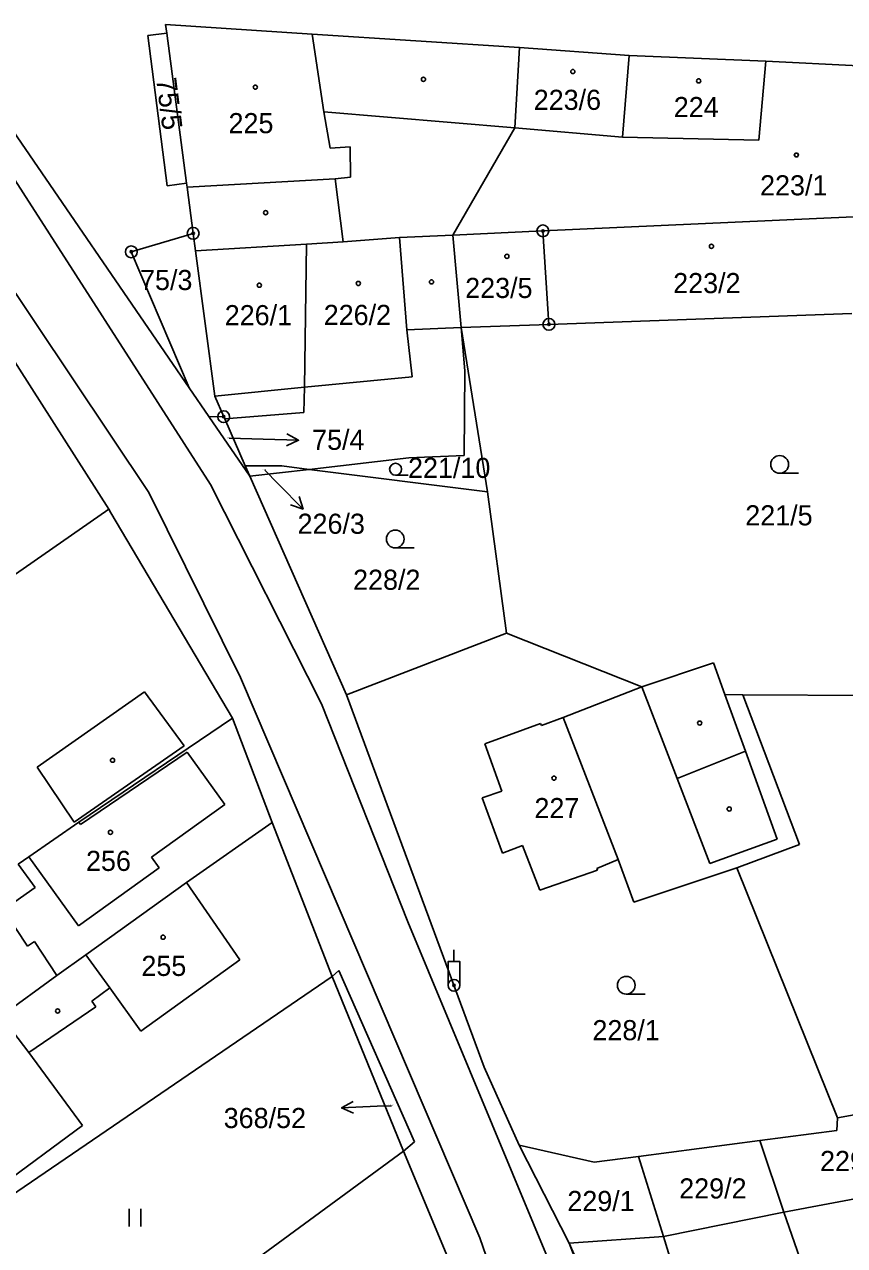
# Model space of a CAD drawing. Extents: x -762263 to -760336, y -1154405 to -1152076.
# Drawn here: x -761538.5 to -761469.2, y -1152630.1 to -1152526.9 of the extents above; entities that cross this region are included whole.
import ezdxf

# ---------------------------------------------------------------- set-up
doc = ezdxf.new("R2010")
doc.units = 0
for name, color, linetype in [('Vrstva 1', 7, 'Continuous'), ('Vrstva 16', 7, 'Continuous'), ('Vrstva 18', 7, 'Continuous'), ('Vrstva 19', 7, 'Continuous'), ('Vrstva 24', 7, 'Continuous'), ('Vrstva 25', 7, 'Continuous'), ('Vrstva 4', 7, 'Continuous')]:
    doc.layers.add(name, color=color, linetype=linetype)

msp = doc.modelspace()

# ---------------------------------------------------------------- linework, layer by layer
at = {"layer": 'Vrstva 1'}
for p, q in [((-761526.57, -1152526.95), (-761526.47, -1152527.69)), ((-761514.18, -1152527.76), (-761526.57, -1152526.95)), ((-761526.47, -1152527.69), (-761528.06, -1152527.89)), ((-761528.06, -1152527.89), (-761526.44, -1152540.58)), ((-761524.81, -1152540.35), (-761526.47, -1152527.69)), ((-761496.67, -1152528.9), (-761514.18, -1152527.76)), ((-761497.08, -1152535.69), (-761496.67, -1152528.9)), ((-761496.67, -1152528.9), (-761487.42, -1152529.57)), ((-761487.42, -1152529.57), (-761487.98, -1152536.48)), ((-761487.42, -1152529.57), (-761475.86, -1152530.04)), ((-761475.86, -1152530.04), (-761476.45, -1152536.72)), ((-761475.86, -1152530.04), (-761468, -1152530.44)), ((-761542.83, -1152531.03), (-761524.57, -1152557.66)), ((-761497.08, -1152535.69), (-761502.31, -1152544.74)), ((-761487.98, -1152536.48), (-761497.08, -1152535.69)), ((-761476.45, -1152536.72), (-761487.98, -1152536.48)), ((-761526.44, -1152540.58), (-761524.81, -1152540.35)), ((-761524.81, -1152540.35), (-761524.76, -1152540.69)), ((-761524.76, -1152540.69), (-761524.24, -1152544.6)), ((-761494.7, -1152544.39), (-761468.46, -1152543.2)), ((-761529.47, -1152546.16), (-761524.24, -1152544.6)), ((-761524.24, -1152544.6), (-761524.04, -1152546.08)), ((-761502.31, -1152544.74), (-761506.82, -1152544.95)), ((-761502.31, -1152544.74), (-761494.7, -1152544.39)), ((-761502.31, -1152544.74), (-761501.61, -1152552.56)), ((-761494.19, -1152552.29), (-761494.7, -1152544.39)), ((-761514.66, -1152545.5), (-761524.04, -1152546.08)), ((-761514.66, -1152545.5), (-761514.85, -1152557.6)), ((-761511.56, -1152545.31), (-761514.66, -1152545.5)), ((-761506.82, -1152544.95), (-761511.56, -1152545.31)), ((-761524.57, -1152557.66), (-761529.47, -1152546.16)), ((-761524.04, -1152546.08), (-761522.42, -1152558.34)), ((-761542.55, -1152550.45), (-761531.37, -1152567.89)), ((-761468.61, -1152551.37), (-761494.19, -1152552.29)), ((-761494.19, -1152552.29), (-761501.61, -1152552.56)), ((-761499.38, -1152566.43), (-761501.61, -1152552.56)), ((-761501.29, -1152556.22), (-761501.61, -1152552.56)), ((-761501.34, -1152563.36), (-761501.29, -1152556.22)), ((-761522.92, -1152560.06), (-761524.57, -1152557.66)), ((-761514.85, -1152557.6), (-761514.88, -1152559.72)), ((-761522.42, -1152558.34), (-761521.66, -1152560.09)), ((-761519.45, -1152565.12), (-761522.92, -1152560.06)), ((-761522.92, -1152560.06), (-761521.66, -1152560.09)), ((-761521.58, -1152560.26), (-761521.66, -1152560.09)), ((-761521.58, -1152560.26), (-761514.88, -1152559.72)), ((-761519.84, -1152564.23), (-761521.58, -1152560.26)), ((-761506.02, -1152563.57), (-761501.34, -1152563.36)), ((-761519.84, -1152564.23), (-761519.45, -1152565.12)), ((-761519.84, -1152564.23), (-761516.76, -1152564.25)), ((-761516.76, -1152564.25), (-761514.44, -1152564.54)), ((-761514.44, -1152564.54), (-761506.02, -1152563.57)), ((-761519.45, -1152565.12), (-761514.44, -1152564.54)), ((-761511.28, -1152583.59), (-761519.45, -1152565.12)), ((-761514.44, -1152564.54), (-761499.38, -1152566.43)), ((-761499.38, -1152566.43), (-761497.76, -1152578.37)), ((-761531.37, -1152567.89), (-761552.58, -1152582.67)), ((-761531.37, -1152567.89), (-761531.19, -1152568.22)), ((-761531.19, -1152568.22), (-761520.93, -1152585.55)), ((-761497.76, -1152578.37), (-761511.28, -1152583.59)), ((-761497.76, -1152578.37), (-761486.33, -1152582.92)), ((-761486.33, -1152582.92), (-761480.3, -1152580.88)), ((-761480.3, -1152580.88), (-761479.33, -1152583.56)), ((-761492.99, -1152585.49), (-761486.33, -1152582.92)), ((-761499.65, -1152615.04), (-761511.28, -1152583.59)), ((-761479.33, -1152583.56), (-761477.82, -1152583.57)), ((-761477.82, -1152583.57), (-761473.01, -1152596.23)), ((-761477.82, -1152583.57), (-761455.83, -1152583.7)), ((-761533.89, -1152594.35), (-761520.93, -1152585.55)), ((-761520.93, -1152585.55), (-761517.57, -1152594.38)), ((-761499.6, -1152587.73), (-761494.89, -1152586)), ((-761494.89, -1152586), (-761494.82, -1152586.18)), ((-761494.82, -1152586.18), (-761492.99, -1152585.49)), ((-761498.18, -1152591.71), (-761499.6, -1152587.73)), ((-761499.82, -1152592.27), (-761498.18, -1152591.71)), ((-761498.12, -1152596.95), (-761499.82, -1152592.27)), ((-761538.11, -1152597.27), (-761533.89, -1152594.35)), ((-761517.57, -1152594.38), (-761524.8, -1152599.45)), ((-761517.57, -1152594.38), (-761512.5, -1152607.38)), ((-761496.43, -1152596.3), (-761498.12, -1152596.95)), ((-761494.97, -1152600.09), (-761496.43, -1152596.3)), ((-761473.01, -1152596.23), (-761478.31, -1152598.2)), ((-761539.02, -1152597.89), (-761538.11, -1152597.27)), ((-761488.34, -1152597.5), (-761490.15, -1152598.25)), ((-761487.03, -1152601.11), (-761488.34, -1152597.5)), ((-761490.1, -1152598.39), (-761494.97, -1152600.09)), ((-761490.15, -1152598.25), (-761490.1, -1152598.39)), ((-761478.31, -1152598.2), (-761487.03, -1152601.11)), ((-761478.31, -1152598.2), (-761469.82, -1152619.33)), ((-761533.3, -1152605.54), (-761524.8, -1152599.45)), ((-761535.75, -1152607.29), (-761533.3, -1152605.54)), ((-761543.8, -1152628.75), (-761512.5, -1152607.38)), ((-761535.75, -1152607.29), (-761540.45, -1152610.73)), ((-761512.5, -1152607.38), (-761511.93, -1152606.87)), ((-761512.5, -1152607.38), (-761506.46, -1152622.12)), ((-761511.93, -1152606.87), (-761505.54, -1152621.35)), ((-761496.7, -1152621.63), (-761499.65, -1152615.04)), ((-761460.67, -1152617.62), (-761469.82, -1152619.33)), ((-761469.82, -1152619.33), (-761469.87, -1152620.39)), ((-761469.87, -1152620.39), (-761476.37, -1152621.24)), ((-761506.46, -1152622.12), (-761545.06, -1152650.41)), ((-761505.54, -1152621.35), (-761506.46, -1152622.12)), ((-761499.73, -1152638.35), (-761506.46, -1152622.12)), ((-761492.49, -1152629.91), (-761496.7, -1152621.63)), ((-761496.7, -1152621.63), (-761490.36, -1152623.06)), ((-761486.61, -1152622.57), (-761476.37, -1152621.24)), ((-761476.37, -1152621.24), (-761474.34, -1152627.29)), ((-761490.36, -1152623.06), (-761486.61, -1152622.57)), ((-761486.61, -1152622.57), (-761484.52, -1152629.33)), ((-761474.34, -1152627.29), (-761458.17, -1152624.21)), ((-761474.34, -1152627.29), (-761484.52, -1152629.33)), ((-761470.41, -1152638.61), (-761474.34, -1152627.29)), ((-761492.49, -1152629.91), (-761484.52, -1152629.33)), ((-761484.52, -1152629.33), (-761481.11, -1152640.38)), ((-761484.68, -1152647.45), (-761492.49, -1152629.91)), ((-761492.49, -1152629.91), (-761473.79, -1152677.53))]:
    msp.add_line(p, q, dxfattribs=at)
at = {"layer": 'Vrstva 16'}
for p, q in [((-761521.21, -1152561.91), (-761518.34, -1152561.99)), ((-761515.341, -1152562.078), (-761518.34, -1152561.99)), ((-761518.2, -1152564.6), (-761517.06, -1152565.76)), ((-761514.951, -1152567.894), (-761517.06, -1152565.76)), ((-761511.707, -1152618.476), (-761508.71, -1152618.34)), ((-761507.5, -1152618.29), (-761508.71, -1152618.34))]:
    msp.add_line(p, q, dxfattribs=at)
for points in [[(-761516.326, -1152561.549), (-761515.341, -1152562.078), (-761516.356, -1152562.549)], [(-761515.299, -1152566.831), (-761514.951, -1152567.894), (-761516.01, -1152567.534)], [(-761510.685, -1152618.93), (-761511.707, -1152618.476), (-761510.731, -1152617.931)]]:
    msp.add_lwpolyline(points, dxfattribs=at)
at = {"layer": 'Vrstva 24'}
for centre, radius in [((-761524.24, -1152544.6), 0.5), ((-761524.24, -1152544.6), 0.1), ((-761494.7, -1152544.39), 0.5), ((-761494.7, -1152544.39), 0.1), ((-761529.47, -1152546.16), 0.5), ((-761529.47, -1152546.16), 0.1), ((-761494.19, -1152552.29), 0.5), ((-761494.19, -1152552.29), 0.1), ((-761521.66, -1152560.09), 0.5), ((-761521.66, -1152560.09), 0.1)]:
    msp.add_circle(centre, radius, dxfattribs=at)
at = {"layer": 'Vrstva 25'}
for p, q in [((-761507.14, -1152565.03), (-761506.068, -1152565.03)), ((-761474.7, -1152564.87), (-761473.1, -1152564.87)), ((-761507.17, -1152571.17), (-761505.57, -1152571.17)), ((-761487.66, -1152608.87), (-761486.06, -1152608.87)), ((-761529.66, -1152628.5), (-761529.66, -1152627)), ((-761528.66, -1152628.5), (-761528.66, -1152627))]:
    msp.add_line(p, q, dxfattribs=at)
msp.add_lwpolyline([(-761473.19, -1152537.83), (-761473.1, -1152537.98), (-761473.19, -1152538.13), (-761473.37, -1152538.13), (-761473.46, -1152537.98), (-761473.37, -1152537.83)], close=True, dxfattribs=at)
for points in [[(-761502.21, -1152606.12), (-761502.21, -1152605.12)], [(-761502.71, -1152608.12), (-761502.71, -1152606.12), (-761501.71, -1152606.12), (-761501.71, -1152608.12)]]:
    msp.add_lwpolyline(points, dxfattribs=at)
for centre, radius in [((-761504.79, -1152531.59), 0.175), ((-761492.17, -1152530.93), 0.175), ((-761518.99, -1152532.25), 0.175), ((-761481.54, -1152531.72), 0.175), ((-761518.12, -1152542.85), 0.175), ((-761480.46, -1152545.69), 0.175), ((-761497.74, -1152546.54), 0.175), ((-761518.65, -1152548.98), 0.175), ((-761510.29, -1152548.83), 0.175), ((-761504.11, -1152548.7), 0.175), ((-761474.7, -1152564.12), 0.75), ((-761507.14, -1152564.528), 0.503), ((-761507.17, -1152570.42), 0.75), ((-761481.45, -1152585.97), 0.175), ((-761531.05, -1152589.11), 0.175), ((-761493.76, -1152590.62), 0.175), ((-761478.96, -1152593.23), 0.175), ((-761531.23, -1152595.2), 0.175), ((-761526.78, -1152604.06), 0.175), ((-761502.21, -1152608.12), 0.5), ((-761487.66, -1152608.12), 0.75), ((-761502.21, -1152608.12), 0.1), ((-761535.69, -1152610.29), 0.175)]:
    msp.add_circle(centre, radius, dxfattribs=at)
at = {"layer": 'Vrstva 4'}
for p, q in [((-761513.2, -1152534.33), (-761514.18, -1152527.76)), ((-761544.34, -1152532.27), (-761522.78, -1152565.81)), ((-761497.08, -1152535.69), (-761513.2, -1152534.33)), ((-761512.68, -1152537.39), (-761513.2, -1152534.33)), ((-761527.99, -1152566.5), (-761548.63, -1152535.63)), ((-761510.97, -1152537.28), (-761512.68, -1152537.39)), ((-761510.94, -1152539.86), (-761510.97, -1152537.28)), ((-761512.24, -1152539.99), (-761524.76, -1152540.69)), ((-761512.24, -1152539.99), (-761510.94, -1152539.86)), ((-761511.56, -1152545.31), (-761512.24, -1152539.99)), ((-761506.18, -1152552.75), (-761506.82, -1152544.95)), ((-761506.18, -1152552.75), (-761501.61, -1152552.56)), ((-761505.74, -1152556.71), (-761506.18, -1152552.75)), ((-761514.85, -1152557.6), (-761505.74, -1152556.71)), ((-761522.42, -1152558.34), (-761514.85, -1152557.6)), ((-761527.99, -1152566.5), (-761520.23, -1152582.13)), ((-761522.78, -1152565.81), (-761513.4, -1152584.33)), ((-761520.23, -1152582.13), (-761500.02, -1152629.46)), ((-761483.36, -1152590.65), (-761486.33, -1152582.92)), ((-761537.42, -1152589.7), (-761528.36, -1152583.34)), ((-761528.36, -1152583.34), (-761525, -1152587.88)), ((-761479.33, -1152583.56), (-761477.59, -1152588.34)), ((-761513.4, -1152584.33), (-761506.1, -1152602.75)), ((-761488.34, -1152597.5), (-761492.99, -1152585.49)), ((-761525, -1152587.88), (-761534.29, -1152594.34)), ((-761524.76, -1152588.44), (-761533.75, -1152594.55)), ((-761524.76, -1152588.44), (-761521.57, -1152592.85)), ((-761483.36, -1152590.65), (-761477.59, -1152588.34)), ((-761477.59, -1152588.34), (-761474.9, -1152595.78)), ((-761534.29, -1152594.34), (-761537.42, -1152589.7)), ((-761480.6, -1152597.84), (-761483.36, -1152590.65)), ((-761527.76, -1152597.3), (-761521.57, -1152592.85)), ((-761533.75, -1152594.55), (-761533.89, -1152594.35)), ((-761474.9, -1152595.78), (-761480.6, -1152597.84)), ((-761538.11, -1152597.27), (-761533.93, -1152603.1)), ((-761527.1, -1152598.21), (-761527.76, -1152597.3)), ((-761539.02, -1152597.89), (-761537.6, -1152599.85)), ((-761533.93, -1152603.1), (-761527.1, -1152598.21)), ((-761524.8, -1152599.45), (-761520.31, -1152605.97)), ((-761537.6, -1152599.85), (-761540.25, -1152601.75)), ((-761540.25, -1152601.75), (-761538.24, -1152604.81)), ((-761506.1, -1152602.75), (-761488.43, -1152645.22)), ((-761538.24, -1152604.81), (-761537.64, -1152604.42)), ((-761537.64, -1152604.42), (-761535.75, -1152607.29)), ((-761531.28, -1152608.34), (-761533.3, -1152605.54)), ((-761520.31, -1152605.97), (-761528.65, -1152611.99)), ((-761531.28, -1152608.34), (-761532.81, -1152609.45)), ((-761528.65, -1152611.99), (-761531.28, -1152608.34)), ((-761532.46, -1152609.93), (-761532.81, -1152609.45)), ((-761538.13, -1152613.79), (-761540.45, -1152610.73)), ((-761538.13, -1152613.79), (-761532.46, -1152609.93)), ((-761533.59, -1152619.96), (-761538.13, -1152613.79)), ((-761544.39, -1152627.92), (-761533.59, -1152619.96)), ((-761500.02, -1152629.46), (-761492.09, -1152652.18))]:
    msp.add_line(p, q, dxfattribs=at)

# ---------------------------------------------------------------- texts
at = {"layer": 'Vrstva 16'}
for s, p in [('75/4', (-761514.193, -1152562.89)), ('226/3', (-761515.423, -1152569.98)), ('368/52', (-761521.662, -1152620.18))]:
    msp.add_text(s, height=1.7, dxfattribs=at).set_placement(p)
at = {"layer": 'Vrstva 18'}
msp.add_text('75/5', height=1.7, rotation=277.31157, dxfattribs=at).set_placement((-761527.376, -1152531.555))
for s, height, p in [('75/3', 1.7, (-761528.728, -1152549.39)), ('75/4', 0.1, (-761521.372, -1152561.91)), ('226/3', 0.1, (-761518.416, -1152564.6)), ('221/10', 1.7, (-761506.09, -1152565.26)), ('221/5', 1.7, (-761477.603, -1152569.27)), ('228/2', 1.7, (-761510.731, -1152574.71)), ('228/1', 1.7, (-761490.513, -1152612.76)), ('368/52', 0.1, (-761507.756, -1152618.29)), ('229/3', 1.7, (-761471.287, -1152623.81)), ('229/2', 1.7, (-761483.183, -1152626.13)), ('229/1', 1.7, (-761492.633, -1152627.19))]:
    msp.add_text(s, height=height, dxfattribs=at).set_placement(p)
at = {"layer": 'Vrstva 19'}
for s, p in [('223/6', (-761495.473, -1152534.17)), ('224', (-761483.643, -1152534.78)), ('225', (-761521.253, -1152536.14)), ('223/1', (-761476.353, -1152541.39)), ('223/2', (-761483.693, -1152549.65)), ('223/5', (-761501.263, -1152550.06)), ('226/1', (-761521.573, -1152552.36)), ('226/2', (-761513.213, -1152552.34)), ('227', (-761495.413, -1152594)), ('256', (-761533.293, -1152598.46)), ('255', (-761528.613, -1152607.33))]:
    msp.add_text(s, height=1.7, dxfattribs=at).set_placement(p)

doc.saveas('drawing.dxf')
